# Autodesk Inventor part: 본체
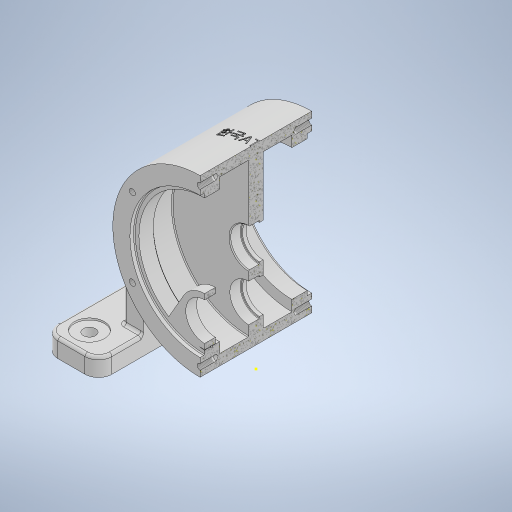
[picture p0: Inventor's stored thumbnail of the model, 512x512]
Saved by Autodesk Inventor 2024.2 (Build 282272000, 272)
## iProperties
Created: 2025-12
Part Number: 본체
Material: 일반
Document SubType Name: Modeling
Designer: home
Density: 1 g/cm^3
Appearance: 기본값
Mass: 2162.62 g
Surface Area: 3079.2 cm^2
Volume: 2162.62 cm^3
Author: home
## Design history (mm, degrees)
sketch "스케치1"
  geometry: L1 (135, -100)-(75, -100); L2 (75, -100)-(75, 100); L3 (75, 100)-(135, 100); L4 (135, 100)-(135, -100); L5 (-75, -100)-(-135, -100); L6 (-135, -100)-(-135, 100); L7 (-135, 100)-(-75, 100); L8 (-75, 100)-(-75, -100); 2 further points
  constraints: 16 end point, 4 parallel, 2 horizontal, 2 perpendicular, 1 midpoint
  dimensions: "d0" = 60 distance between parallel lines of L2 L4; "d1" = 60 distance between parallel lines of L6 L8; "d2" = 135 distance from line of point (0, 0) L4; "d3" = 135 distance from line of point (0, 0) L6; "d4" = 100 vertical distance of point (-105, -100) point (0, 0); "d5" = 100 distance from line of L7 point (0, 0); "d6" = 100 distance from line of point (0, 0) L1; "d7" = 100 distance from line of point (0, 0) L3
extrude "돌출1" new body sketch "스케치1" distance "d8" = 20; taper "d9" = 0 deg
sketch "스케치2"
  geometry: C1 r 97 at (0, 120); 1 further point
  constraints: 1 centre point, 1 vertical alignment
  dimensions: "d11" = 194 diameter of C1
extrude "돌출2" join sketch "스케치2" stored distance "d12" = 124; taper "d13" = 0 deg
sketch "스케치3"
  geometry: L1 (-135, 20)-(-75, 20) reference; L2 (75, 20)-(135, 20) reference; L3 (97, 120)-(97, 20); L4 (-97, 120)-(-97, 20); L5 (-75, 58.486)-(-75, 20); L6 (75, 20)-(75, 58.486); A1 r 97 centre (0, 120) between (97, 120) and (-97, 120) reference; 1 further point
  constraints: 8 end point, 4 point on circle, 2 perpendicular, 2 point on line, 2 tangent, 2 vertical
extrude "돌출3" join sketch "스케치3" stored distance "d14" = 100; taper "d15" = 0 deg
extrude "돌출4" join sketch "스케치3" stored distance "d16" = 100; taper "d17" = 0 deg
sketch "스케치4"
  geometry: L1 (120, 142.24)-(120, -159.656); L2 (0, 100)-(0, -100) reference; L3 (217, 62)-(23, 62) reference; L4 (23, -62)-(217, -62) reference; L5 (141, 8)-(141, -4); L6 (141, -4)-(120, -4); L7 (120, -4)-(120, 7.39); L8 (120, -4)-(139, -4); L9 (120, -13.476)-(120, -4); L10 (120, 62)-(198, 62); L11 (198, 62)-(198, 57); L12 (198, 57)-(120, 57); L13 (120, 57)-(120, 62); L14 (120, -62)-(198, -62); L15 (198, -62)-(198, -57); L16 (198, -57)-(120, -57); L17 (120, -57)-(120, -62); L18 (120, -57)-(193, -57); L19 (193, -57)-(193, -40); L20 (193, -40)-(120, -40); L21 (120, -40)-(120, -57); L22 (120, -40)-(205, -40); L23 (205, -40)-(205, -8); L24 (205, -8)-(120, -8); L25 (120, -8)-(120, -40); L26 (120, -4)-(139, -4); L27 (139, -4)-(139, -8); L28 (139, -8)-(120, -8); L29 (120, -8)-(120, -4); L30 (256.411, 0)-(-60.055, 0); L31 (205, 40)-(205, 8); L32 (205, 8)-(120, 8); L33 (120, 40)-(205, 40); L34 (141, 57)-(193, 57); L35 (193, 57)-(193, 40); L36 (193, 40)-(141, 40); L37 (141, 40)-(141, 57); L38 (67.5, 77.208)-(67.5, -163.094); L39 (120, 50)-(58.486, 50) reference; L40 (67.5, 57)-(88.5, 57); L41 (88.5, 57)-(88.5, 50); L42 (88.5, 50)-(67.5, 50); L43 (67.5, 50)-(67.5, 57); L44 (67.5, 50)-(89.75, 50); L45 (89.75, 50)-(89.75, 48.05); L46 (89.75, 48.05)-(67.5, 48.05); L47 (67.5, 48.05)-(67.5, 50); L48 (67.5, 48.05)-(88.5, 48.05); L49 (88.5, 48.05)-(88.5, 36.05); L50 (88.5, 36.05)-(67.5, 36.05); L51 (67.5, 36.05)-(67.5, 48.05); L52 (120, -4)-(67.5, -4); L53 (120, -8)-(67.5, -8); L54 (120, 8)-(67.5, 8); L55 (86.5, -4)-(86.5, -8); L56 (67.5, -4)-(88.5, -4); L57 (88.5, -4)-(88.5, 8); L58 (88.5, 8)-(67.5, 8); L59 (67.5, 8)-(67.5, -4); L60 (86.5, -8)-(67.5, -8); 24 further points
  constraints: 112 end point, 21 parallel, 13 perpendicular, 13 point on line, 12 horizontal, 4 symmetric about line, 2 midpoint, 2 vertical, 1 collinear
  dimensions: "d18" = 120 distance between parallel lines of L2 L1; "d19" = 66 distance between parallel lines of L6 L3; "d20" = 42 diameter of L5 L1; "d22" = 5 distance of L10.end L11.end; "d23" = 156 diameter of L11 L1; "d24" = 5 distance of L14.end L15.end; "d25" = 156 diameter of L15 L1; "d26" = 22 distance between parallel lines of L4 L20; "d27" = 146 diameter of L19 L1; "d28" = 32 distance of L22.end L23.end; "d29" = 170 diameter of L23 L1; "d30" = 38 diameter of L27 L1; "d32" = 22 distance between parallel lines of L33 L3; "d35" = 146 diameter of L35 L1; "d37" = 42 diameter of L41 L38; "d38" = 44.5 diameter of L45 L38; "d39" = 1.95 distance between parallel lines of L46 L39; "d40" = 12 distance between parallel lines of L50 L46; "d41" = 42 diameter of L49 L38; "d42" = 19 distance of L6.end L8.end; "d43" = 42 diameter of L57 L38; "d44" = 38 diameter of L55 L38; "d47" = 52.5 distance between parallel lines of L38 L1
revolve "회전1" stored, may be unused: angle "d31" = 360 deg
revolve "회전2" stored, may be unused: angle "d45" = 90 deg
revolve "회전3" stored, may be unused: angle "d46" = 90 deg
fillet "모깎기1" dims "d48" = 15
sketch "스케치5"
  geometry: L1 (-135, 85)-(-135, -85) reference; L2 (-120, -100)-(-90, -100) reference; L3 (-75, -85)-(-75, -50) reference; L4 (-75, -50)-(-97, -50) reference; L5 (-97, -50)-(-97, 50) reference; L6 (-97, 50)-(-75, 50) reference; L7 (-75, 50)-(-75, 85) reference; L8 (-90, 100)-(-120, 100) reference; L9 (90, -100)-(120, -100) reference; L10 (135, -85)-(135, 85) reference; L11 (120, 100)-(90, 100) reference; L12 (75, 85)-(75, 50) reference; L13 (75, 50)-(97, 50) reference; L14 (97, 50)-(97, -50) reference; L15 (97, -50)-(75, -50) reference; L16 (75, -50)-(75, -85) reference; A1 r 15 centre (-120, 85) between (-120, 100) and (-135, 85) reference; A2 r 15 centre (-120, -85) between (-135, -85) and (-120, -100) reference; A3 r 15 centre (-90, -85) between (-90, -100) and (-75, -85) reference; A4 r 15 centre (-90, 85) between (-75, 85) and (-90, 100) reference; A5 r 15 centre (90, -85) between (75, -85) and (90, -100) reference; A6 r 15 centre (120, -85) between (120, -100) and (135, -85) reference; A7 r 15 centre (120, 85) between (135, 85) and (120, 100) reference; A8 r 15 centre (90, 85) between (90, 100) and (75, 85) reference; 1 further point
  node "투영된 루프1"
sketch "스케치6"
  geometry: L1 (0, -159.385)-(0, 176.547); L2 (184.988, 0)-(-326.881, 0); L3 (90, -100)-(120, -100) reference; L4 (135, -85)-(135, 85) reference; L5 (120, 100)-(90, 100) reference; L6 (75, 85)-(75, 50) reference; L7 (75, 50)-(97, 50) reference; L8 (97, 50)-(97, -50) reference; L9 (97, -50)-(75, -50) reference; L10 (75, -50)-(75, -85) reference; C1 r 16.5 at (110, -75); C2 r 16.5 at (110, 70.867); C3 r 16.5 at (-110, -75); C4 r 16.5 at (-110, 75); C5 r 6.75 at (110, -75); C6 r 6.75 at (110, 70.867); C7 r 6.75 at (-110, 75); C8 r 6.75 at (-110, -75); A1 r 15 centre (90, -85) between (75, -85) and (90, -100) reference; A2 r 15 centre (120, -85) between (120, -100) and (135, -85) reference; A3 r 15 centre (120, 85) between (135, 85) and (120, 100) reference; A4 r 15 centre (90, 85) between (90, 100) and (75, 85) reference; 1 further point
  constraints: 8 centre point, 4 coincident, 4 end point, 1 horizontal, 1 vertical
  dimensions: "d49" = 33 diameter of C1; "d50" = 33 diameter of C2; "d51" = 33 diameter of C3; "d52" = 33 diameter of C4; "d53" = 110 distance from line of L1 C2.centre; "d54" = 110 distance from line of L1 C4.centre; "d55" = 75 distance from line of L2 C4.centre; "d56" = 75 distance from line of L2 C3.centre; "d57" = 75 distance from line of L2 C1.centre; "d58" = 110 distance from line of L1 C1.centre; "d59" = 110 distance from line of C3.centre L1; "d62" = 13.5 diameter of C5; "d63" = 13.5 diameter of C6; "d64" = 13.5 diameter of C7; "d65" = 13.5 diameter of C8
  node "투영된 루프2"
extrude "돌출5" cut sketch "스케치6" distance "d60" = 2; taper "d61" = 0 deg
extrude "돌출6" cut sketch "스케치6" extent not by distance; stored distance "d66" = 0; taper "d67" = 0 deg
node "작업 평면3"
sketch "스케치7"
  geometry: L1 (-148.801, -5.955)-(165.111, -5.955); L2 (-23.383, -32.455)-(-43.991, -68.149); L3 (23.383, -32.455)-(39.928, -61.112); L4 (0, -120)-(0, 226.545); C1 r 21 at (0, -45.955); A1 r 22.25 centre (0, -52.5) between (-10.174, -72.287) and (10.174, -72.287) reference; A2 r 27 centre (0, -45.955) between (-23.383, -32.455) and (23.383, -32.455); A3 r 73 centre (0, 0) between (-10.174, -72.287) and (10.174, -72.287) reference; A4 r 73 centre (0, 0) between (5.368, -72.802) and (-5.368, -72.802) reference; 1 further point
  constraints: 8 end point, 3 point on circle, 2 centre point, 2 tangent, 1 coincident, 1 horizontal, 1 vertical, 1 vertical alignment
  dimensions: "d70" = 54 diameter of A2; "d71" = 40 distance from line of L1 A2.centre; "d72" = 4.02262 distance from line of A4.centre L3; "d73" = 30 deg angle of L3 L4; "d74" = 30 deg angle of L4 L2; "d75" = 42 diameter of C1
extrude "돌출7" join sketch "스케치7" stored distance "d76" = 12; taper "d77" = 0 deg
sketch "스케치9"
  geometry: L1 (0, 0)-(125.513, 72.465); L2 (0, 0)-(0, 156.228); L3 (0, 0)-(200.697, -115.873); L4 (0, 0)-(0, -237.75); L5 (0, 0)-(-224.304, 129.502); L6 (0, 0)-(-206.493, -119.219); C1 r 97 at (0, 0) reference; C2 r 78 at (0, 0) reference; C3 r 21 at (0, 0) reference; A1 r 87 centre (0, 0) between (0, 87) and (75.344, 43.5); 5 further points
  constraints: 12 end point, 6 point on circle, 5 point on line, 1 centre point, 1 coincident, 1 vertical
  dimensions: "d86" = 174 diameter of A1; "d94" = 60 deg angle of L1 L2; "d95" = 60 deg angle of L5 L2; "d96" = 60 deg angle of L3 L1; "d97" = 60 deg angle of L3 L4; "d98" = 60 deg angle of L6 L4
hole "구멍2" sketch "스케치9" diameter "d87" = 6.647; stored, may be unused: countersink angle "d91" = 90 deg, drill point angle "d93" = 118 deg; dims "d88" = 16, "d89" = 4, "d90" = 2, "d92" = 18
hole "구멍3" sketch "스케치9" diameter "d99" = 6.647; stored, may be unused: countersink angle "d103" = 90 deg, drill point angle "d105" = 118 deg; dims "d100" = 16, "d101" = 4, "d102" = 2, "d104" = 18
fillet "모깎기2" dims "d106" = 3
fillet "모깎기4" dims "d108" = 3
chamfer "모따기1" distance "d109" = 1; stored, may be unused: second distance "d110" = 2, angle "d111" = 45 deg
sketch "스케치10"
  geometry: L1 (-75, 22.196)-(-75, 58.486) reference; L2 (-75, 0)-(-75, 17) reference; L3 (-75, 17)-(-75, 22.196) reference; L4 (75, 58.486)-(75, 17) reference; L5 (75, 17)-(75, 0) reference; L6 (0, 120.325)-(0, -118.414); L7 (-75, 8)-(-36.6, 30.17); L8 (-75, 0)-(-90, 0) reference; L9 (75, 8)-(36.6, 30.17); L10 (-78, 23)-(-94, 23) reference; L11 (-75, 22.196)-(-75, 58.486) reference; L12 (-94, 23)-(-94, 96.063) reference; C1 r 3.324 at (75.344, 76.5) reference; C2 r 3.324 at (0, 33) reference; C3 r 3.324 at (-75.344, 76.5) reference; C4 r 3.324 at (-75.344, 163.5) reference; C5 r 3.324 at (75.344, 163.5) reference; C6 r 3.324 at (0, 207) reference; C7 r 78 at (0, 120) reference; C8 r 97 at (0, 120) reference; C9 r 97 at (0, 120) reference; C10 r 97 at (0, 120) reference; C11 r 78 at (0, 120) reference; A1 r 6 centre (-78, 17) between (-75, 22.196) and (-78, 23) reference; A2 r 97 centre (0, 120) between (-94, 96.063) and (-75, 58.486) reference; A3 r 97 centre (0, 120) between (-94, 96.063) and (-78, 62.337) reference; A4 r 97 centre (0, 120) between (-94, 96.063) and (-75, 58.486) reference; A5 r 97 centre (0, 120) between (78, 62.337) and (94, 96.063) reference; A6 r 97 centre (0, 120) between (78, 62.337) and (94, 96.063) reference; 15 further points
  constraints: 6 end point, 2 symmetric about line, 2 vertical, 1 point on line, 12 other
  dimensions: "d112" = 8 distance from line of L8 L7.start; "d113" = 60 deg angle of L7 L1
  node "투영된 루프3"
  node "투영된 루프4"
  node "투영된 루프5"
extrude "돌출8" join sketch "스케치10" stored distance "d114" = 12; taper "d115" = 0 deg
extrude "돌출9" join sketch "스케치10" stored distance "d116" = 12; taper "d117" = 0 deg
fillet "모깎기5" dims "d118" = 3
fillet "모깎기6" dims "d119" = 3
sketch "스케치13"
  geometry: 1 further point
node "작업 평면4"
fillet "모깎기8" dims "d121" = 0.6
chamfer "모따기2" distance "d122" = 1; stored, may be unused: second distance "d123" = 2, angle "d124" = 45 deg
sketch "스케치14"
  geometry: 2 further points
  constraints: 1 other
feature "엠보싱1" sketch "스케치14" dims "d125" = 0.5, "d126" = 0
revolve "회전4" stored, may be unused: angle "d127" = 90 deg
revolve "회전5" stored, may be unused: angle "d128" = 90 deg
chamfer "모따기3" distance "d129" = 1; stored, may be unused: second distance "d130" = 2, angle "d131" = 45 deg
chamfer "모따기4" distance "d132" = 1; stored, may be unused: second distance "d133" = 2, angle "d134" = 45 deg
node "솔리드1"
mirror "미러1"
feature "A9D066F2-1C7D-4E18-AEED-F7BC21143FA4" dims "d87" = 6.647, "d88" = 16, "d89" = 4, "d90" = 2, "d91" = 90 deg, "d92" = 18, "d93" = 118 deg
other parameters: "d68" = -11
